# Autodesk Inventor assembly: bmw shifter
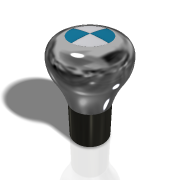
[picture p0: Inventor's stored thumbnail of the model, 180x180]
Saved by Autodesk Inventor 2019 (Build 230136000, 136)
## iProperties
Created: 2016-11
Part Number: bmw shifter
Document SubType Name: Assembly
Designer: Newberry
Author: Newberry
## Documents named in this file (4)
- H:\My Drive\3D Printing\BMW Shifter\bmw shifter.iam
- H:\My Drive\3D Printing\BMW Shifter\necked colid shift knob.ipt
- H:\My Drive\3D Printing\BMW Shifter\Part4.ipt
- H:\My Drive\3D Printing\BMW Shifter\Insert.ipt
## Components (6 placed, 3 different names)
1. Shift Knob Body — Mate:1, Flush:2, Mate:2, Mate:3, Mate:4, Mate:5, Mate:6, Mate:7, Mate:8
2. Collar — Mate:1, Flush:2
3. Insert:1 — Angle:2, Mate:3, Mate:4, Angle:3
4. Insert:2 — Angle:1, Mate:2, Angle:2, Angle:4
5. Insert:3 — Angle:3, Mate:5, Mate:6
6. Insert:4 — Angle:4, Mate:7, Mate:8
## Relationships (13: Mate 8, Angle 4, Flush 1)
- Mate:1: Shift Knob Body ↔ Collar
- Flush:2: Shift Knob Body ↔ Collar
- Angle:1: Insert:2
- Mate:2: Shift Knob Body ↔ Insert:2
- Angle:2: Insert:1 ↔ Insert:2
- Mate:3: Shift Knob Body ↔ Insert:1
- Mate:4: Shift Knob Body ↔ Insert:1
- Angle:3: Insert:1 ↔ Insert:3
- Mate:5: Shift Knob Body ↔ Insert:3
- Mate:6: Shift Knob Body ↔ Insert:3
- Angle:4: Insert:2 ↔ Insert:4
- Mate:7: Shift Knob Body ↔ Insert:4
- Mate:8: Shift Knob Body ↔ Insert:4
